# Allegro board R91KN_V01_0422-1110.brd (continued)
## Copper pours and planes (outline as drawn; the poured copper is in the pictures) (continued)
+1V on L3_INNER: 86.25,55.9 88.35,55.9 88.55,55.7 89.05,55.7 89.35,55.4 93.25,55.4 93.45,55.2 93.45,54.6 93.15,54.3 87.05,54.3 86.75,54.6 86.05,54.6 85.75,54.9 85.75,55.4
+1V_LDOOUT on BOTTOM: 48.25,44.8 51.55,44.8 51.95,44.4 53.75,44.4 53.85,44.5 53.85,49.3 52.85,50.3 51.05,50.3 50.45,50.9 49.85,50.9 49.75,50.8 49.75,48.3 50.75,47.3 50.75,46 50.35,45.6 48.15,45.6 47.95,45.4 47.95,45.1
+3.3V_BUS on TOP: 12.25,93.1 12.05,92.9 10.75,92.9 10.05,93.6 10.05,98.3 10.25,98.5 11.65,98.5 12.25,97.9
+3.3V_BUS on TOP: 55.14,6.59 54.95,6.4 52.75,6.4 52.35,6.8 52.35,8.08 52.45,8.18 52.45,13 52.85,13.4 56.95,13.4 57.05,13.3 57.05,12.5 56.85,12.3 56.45,12.3 55.75,11.6 55.75,10.95 55.14,10.34
+3.3V_BUS on BOTTOM: 10.55,98.6 14.75,98.6 18.75,94.6 18.75,91.4 18.15,90.8 18.15,87 16.95,85.8 16.95,71 20.05,67.9 27.65,67.9 33.25,73.5 35.65,73.5 36.95,72.2 36.95,70.3 30.65,64 18.85,64 14.55,68.3 14.55,87.5 15.65,88.6 15.65,92.2 13.05,94.8 10.35,94.8 9.95,95.2 9.95,98
+3.3V_BUS on BOTTOM: 54.99,2.92 54.91,2.84 54.41,2.84 54.31,2.95 54.31,5.66 54.25,5.71 54.08,5.71 54,5.64 54,3 53.85,2.84 53.44,2.84 53.31,2.97 53.31,5.84 52.15,7 52.15,7.39 52.04,7.5 52.04,17.37 52.45,17.78 66.57,17.78 66.78,17.58 66.78,16.53 65.95,15.7 62.85,15.7 60.31,13.16 57.4,13.16 57.1,12.85 57.1,10.62 56.92,10.44 55.5,10.44 55.09,10.03 55.09,5.92 54.99,5.82
+3.3V_BUS on BOTTOM: 73.56,88.06 74.04,88.06 74.38,87.73 74.38,87.07 74.55,86.9 77.55,86.9 78.13,87.48 78.13,91.74 80.04,93.65 90.6,93.65 90.81,93.45 90.81,84.8 87.97,81.96 87.97,81.24 87.65,80.92 86.95,80.92 86.17,81.7 85.65,81.7 85.25,81.3 85.25,81 85.17,80.92 77.23,80.92 76.85,81.3 76.85,82 75.81,83.04 74.79,83.04 73.25,84.58 73.25,87.76
+3.3V_BUS on L3_INNER: 52.45,13 52.45,6.8 52.85,6.4 54.95,6.4 55.15,6.6 55.15,8.2 58.25,11.3 58.35,11.3 61.65,14.6 61.65,52.7 62.25,53.3 62.25,58.5 61.85,58.9 57.18,58.9 40.79,75.29 40.79,94.39 42.21,95.81 70.94,95.81 75.67,91.08 115.14,91.08 122.25,98.2 122.25,101.22 121.57,101.9 31.67,101.9 28.8,99.03 28.8,75.25 52.35,51.7 52.35,13.1
+3.3V_DPB on TOP: 12.95,96 14.85,96 15.35,95.5 15.35,90.9 14.65,90.2 13.75,90.2 13.45,90.5 13.45,91.7 12.55,92.6 12.55,95.6
+3.3V_DPB on TOP: 13.55,88.8 14.95,88.8 15.25,88.5 15.25,86.9 15.05,86.7 12.45,86.7 12.35,86.8 12.35,87.6
+3.3V_DPB on BOTTOM: 13.55,91.5 14.75,91.5 15.15,91.1 15.15,88.6 14.35,87.8 13.35,87.8 12.65,88.5 12.65,89.7 13.45,90.5 13.45,91.4
+5V on BOTTOM: 42.55,46.2 44.35,46.2 44.55,46.4 44.55,47.1 44.75,47.3 45.55,47.3 45.75,47.5 45.75,49.6 45.55,49.8 43.15,49.8 42.35,49 42.35,46.4
+5V_VGAH on TOP: 5.75,94 8.85,94 9.35,93.5 9.35,92.4 8.85,91.9 6.05,91.9 5.45,92.5 5.45,93.7
+5V_VGAH on L3_INNER: 5.45,93.8 7.55,93.8 8.75,92.6 9.35,92.6 9.55,92.4 9.55,88.3 5.85,84.6 2.15,84.6 1.85,84.9 1.85,87.4 4.95,90.5 4.95,93.3
+12V_BUS on TOP: 46.3,6.35 46.15,6.5 46.15,16.84 46.43,17.12 49.33,17.12 49.58,16.87 49.58,15.94 50.22,15.3 51.15,15.3 51.61,14.84 51.61,8.47 50.65,7.51 49.44,7.51 48.13,6.2 48.13,6.2 47.98,6.05 47.98,2.74 47.85,2.62 47.45,2.62 47.32,2.74 47.32,5.61 47.24,5.69 47.07,5.69 46.99,5.61 46.99,2.67 46.89,2.57 46.43,2.57 46.3,2.69
+12V_BUS on TOP: 161.95,30.6 162.55,30 162.55,28.7 162.35,28.5 160.65,28.5 160.15,29 160.15,31.9 160.35,32.1 161.75,32.1 161.95,31.9
+12V_BUS on TOP: 132.75,97.4 136.05,97.4 136.35,97.1 137.85,97.1 138.25,97.5 138.25,99.2 136.65,100.8 135.45,100.8 132.05,104.2 129.55,104.2 129.35,104 129.35,100.8
+12V_BUS on TOP: 20.15,106.7 27.45,106.7 28.65,105.5 28.65,100.5 27.95,99.8 26.65,99.8 25.85,99 25.85,94.4 26.25,94 26.25,91.8 26.05,91.6 25.35,91.6 24.15,92.8 21.25,92.8 19.85,94.2 19.85,106.4
+12V_BUS on BOTTOM: 47.96,6.05 47.96,3 47.78,2.82 47.5,2.82 47.29,3.02 47.29,5.66 47.24,5.71 47.04,5.71 46.99,5.66 46.99,2.9 46.89,2.79 46.41,2.79 46.3,2.9 46.3,5.77 46.25,5.82 46.25,6.3 46.25,6.3 46.25,8.49 46.15,8.59 46.15,13.94 46.18,13.97 46.18,15.13 46.35,15.3 49.12,15.3 50.25,14.17 51.38,14.17 51.61,13.94 51.61,8.66 50.45,7.5 49.41,7.5
+12V_BUS on L3_INNER: 164.07,110.39 166.65,107.81 166.65,54.73 166.62,54.69 166.62,30.63 165.1,29.11 152.91,29.11 151.99,30.02 151.99,35.79 164.12,47.91 164.12,84.93 146.62,102.43 31.28,102.43 27.55,98.7 27.55,75.8 51.38,51.97 51.38,25.61 51.45,25.55 51.45,8.9 49.05,6.5 46.25,6.5 45.55,7.2 45.55,12.1 44.25,13.4 31.35,13.4 29.9,14.85 29.9,27.1 36.55,33.75 36.55,40.43 24.28,52.7 24.28,63.8 11.38,76.71 11.38,107.47 14.3,110.39
+VDDC on TOP: 56.45,85.1 57.75,86.4 57.75,96.66 57.56,96.85 55,96.85 51.35,93.2 46.55,93.2 44.55,91.2 44.55,89.53 42.88,87.86 42.88,85.47 43.25,85.1
+VDDC on BOTTOM: 43.45,84.7 56.55,84.7 57.55,85.7 57.55,87.3 59.25,89 59.25,92.7 58.05,93.9 45.45,93.9 42.35,90.8 42.35,85.8
+VDDC on BOTTOM: 55.55,70.5 55.76,70.29 55.75,70.28 55.75,67.74 53.21,65.2 53.21,62.71 53.85,62.08 53.85,50.9 53.55,50.6 51.15,50.6 50.45,51.3 50.45,68.18 52.77,70.5
+VDDC on L3_INNER: 93.83,70.53 93.83,56.9 92.53,55.6 88.95,55.6 87.86,56.69 86.92,56.69 85.15,58.46 85.15,60.6 84.85,60.9 70.82,60.9 64.67,67.06 63.45,67.06 62,68.5 49.15,68.5 41.45,76.2 41.45,91.2 45.12,94.87 64.39,94.87 75.13,84.12 91.87,84.12 96.27,79.73 96.27,76.15 95.38,75.26 95.35,75.26 95.35,72.05
+VDDC_SOURCE on TOP: 40.35,88.9 40.55,89.1 40.55,95.87 44.68,100 44.68,106.43 43.76,107.34 41.02,107.34 39.29,105.61 29.62,105.61 29.16,105.16 29.16,100 29.54,99.62 31.65,99.62 32.18,99.09 32.18,89.31 32.59,88.9
GND on TOP (solid shape): 76.65,91.1 74.65,91.1 74.65,92.7 76.65,92.7
GND on TOP (solid shape): outline of 188 points within 109,34.8 114.5,40.15
GND on TOP (solid shape): outline of 205 points within 65.8,77.85 71.3,83.35
GND on TOP (solid shape): outline of 208 points within 109,77.85 114.5,83.35
GND on TOP (solid shape): outline of 218 points within 3.1,102.59 8.59,108.08
GND on TOP (solid shape): outline of 218 points within 65.8,34.65 71.3,40.15
GND on BOTTOM (solid shape): outline of 198 points within 109,34.65 114.5,40.15
GND on BOTTOM (solid shape): outline of 205 points within 65.8,77.85 71.3,83.35
GND on BOTTOM (solid shape): outline of 218 points within 65.8,34.65 71.3,40.15
GND on BOTTOM (solid shape): outline of 218 points within 109,77.85 114.5,83.35
GND on TOP: 161.16,92.03 165.36,92.03 165.56,91.83 165.56,88.13 165.36,87.93 161.06,87.93 160.96,88.03 160.96,91.83
GND on TOP: 4.15,99 7.65,99 9.65,97 9.65,94.9 9.05,94.3 4.15,94.3 3.55,94.9 3.55,98.4
GND on TOP: 44.96,16.59 45.8,17.42 49.43,17.42 49.43,17.42 49.85,17 49.85,16.2 50.35,15.7 51.45,15.7 51.65,15.9 51.65,17.4 51.45,17.6 51.05,17.6 51.05,18.5 50.85,18.7 49.75,18.7 49.63,18.82 49.63,19.28 49.43,19.48 45.44,19.48 44.45,20.47 44.45,21.92 44.12,22.25 36.35,22.25 34.11,20.01 34.11,14 34.52,13.59 44.55,13.59 44.96,14
GND on TOP: 129.55,88.5 132.25,88.5 132.95,89.2 132.95,93.5 132.55,93.9 129.65,93.9 129.25,93.5 129.25,88.8
GND on TOP: 27.41,88.77 26.62,89.56 26.62,98.68 27.03,99.09 31.09,99.09 31.83,98.35 31.83,88.98 31.62,88.77
GND on TOP: 41.02,95.63 41.02,89.6 41.54,89.08 43.21,89.08 43.74,89.61 43.74,95.76 43.23,96.27 41.66,96.27
GND on TOP: 146.82,78.9 149,78.9 149.4,78.49 149.4,65.61 148.97,65.18 146.81,65.18 146.38,65.61 146.38,78.47
GND on TOP: 58.15,96.9 59.45,96.9 60.35,96 60.35,87.9 59.95,87.5 58.65,87.5 58.45,87.7 58.45,89.1 57.95,89.6 57.95,96.7
GND on TOP: 33.15,106.5 38.75,106.5 39.05,106.8 39.05,109.4 38.85,109.6 32.95,109.6 32.55,109.2 32.55,107.1
GND on TOP: 138.85,96.2 145.55,96.2 145.85,96.5 145.85,97.7 145.55,98 138.75,98 138.55,97.8 138.55,96.5
GND on TOP: 54.29,103.9 56.75,103.9 57.12,103.53 57.12,99.42 56.95,99.24 54.53,99.24 54.19,99.58 54.19,103.8
GND on BOTTOM: 69.78,69.84 69.78,67.07 69.62,66.91 68.31,66.91 68.11,66.71 68.11,66.03 68.02,65.94 67.11,65.94 66.91,66.14 66.91,67.64 67.02,67.73 68.11,67.73 68.24,67.86 68.24,69.78 68.39,69.92 69.7,69.92
GND on BOTTOM: 72.25,54.6 74.26,54.6 74.85,55.2 76.23,55.2 76.4,55.02 76.4,53.85 76.15,53.6 75.75,53.6 75.45,53.3 75.45,51.5 75.25,51.3 73.65,51.3 73.15,51.8 72.15,51.8 71.85,52.1 71.85,54.2
GND on BOTTOM: 48.7,39.05 47.25,39.05 46.35,38.15 46.35,34.3 46.65,34 48.95,34 49.25,34.3 49.25,38.5
GND on BOTTOM: 48.45,48 49.05,48 49.35,48.3 49.35,50.8 48.95,51.2 46.55,51.2 46.05,50.7 46.05,48.5 46.12,48.43 48.02,48.43
GND on BOTTOM: 40.55,19.6 44.15,19.6 44.45,19.9 44.95,19.9 45.35,19.5 45.35,17.4 44.85,16.9 41.15,16.9 40.05,18 40.05,19.1
GND on BOTTOM: 28.63,88.9 27.05,90.47 27.05,99.09 28.19,100.23 35.08,100.23 35.74,99.57 35.74,90.14 34.49,88.9
GND on BOTTOM: 44.95,47 47.65,47 47.85,46.8 47.85,41.5 47.65,41.3 45.05,41.3 44.85,41.5 44.85,46.9
GND on BOTTOM: 49.62,31.27 56.16,31.27 56.26,31.17 56.26,28.4 55.96,28.09 49.56,28.09 49.35,28.3 49.35,31
GND on BOTTOM: 71.19,46.02 74.26,46.02 74.26,46.01 74.84,46.01 74.95,45.9 74.95,44.65 74.21,43.91 73.32,43.91 72.97,43.56 70.48,43.56 70.31,43.74 70.31,45.87 70.45,46.01 71.18,46.01
GND on BOTTOM: 51.75,17.5 51.85,17.4 51.85,16 51.15,15.3 49.95,15.3 49.45,15.8 47.45,15.8 47.45,17.6 49.25,19.4 50.65,19.4 51.75,18.3
GND on L2_INNER: 0.62,5.05 0.55,5.12 0.55,109.6 1.55,110.59 166.75,110.59 167.07,110.28 167.07,14.41 166.87,14.21 166.38,14.21 166.38,14.2 148.85,14.2 148.15,13.5 140.05,13.5 138.57,12.02 138.57,11.62 136.45,9.5 128.55,9.5 127.65,8.6 127.65,6.88 126.46,5.69 126.46,5.6 58.95,5.6 58.95,8.71 57.84,9.81 56.32,9.81 54.81,8.29 54.81,6.2 46.12,6.2 46.12,11.21 46.13,11.22 45.87,12.33 44.36,13.76 42.58,13.78 41.97,13.65 40.86,12.8 34.61,12.8 33.93,13.48 15.2,13.48 14.37,12.64 14.37,5.05
GND on L3_INNER: 0.56,68.03 0.62,68.09 16.82,68.09 16.95,67.96 16.95,41.5 16.65,41.2 16.65,22.6 17.75,21.5 18.35,21.5 18.95,22.1 18.95,23.6 20.15,24.8 20.15,28.91 23.52,32.28 25.35,32.28 26.67,30.96 26.67,22.52 28.32,20.87 28.32,15.05 27.56,14.3 20.6,14.3 20.05,13.75 14.75,13.75 14.44,13.44 14.44,13.11 14.45,13.1 14.45,5.63 13.87,5.04 0.64,5.04 0.56,5.13
GND on L3_INNER: 58.75,11.03 62.35,14.62 62.35,40.4 62.95,41 73.35,41 75.75,43.4 75.75,47.7 81.72,53.67 84.05,53.67 84.71,54.33 86.72,54.33 87.09,53.96 88.91,53.96 88.93,53.95 93.83,53.95 95,52.78 95,49.4 95.47,48.93 95.47,47.08 95.86,46.69 95.86,45.16 99.64,41.39 99.64,41.35 110.25,30.74 110.29,30.74 128.75,12.27 128.75,8.28 128.56,8.09 128.65,8 128.65,6.6 128.35,6.3 59.15,6.3 58.75,6.7
VDDC_PHASE on TOP: 45.8,103.86 45.8,99.72 44.98,98.91 44.98,94.95 45.85,94.08 51.51,94.08 53.82,96.39 53.82,105.54 53.54,105.82 51.08,105.82 50.44,106.45 50.44,108.38 50.19,108.64 48.11,108.64 47.83,108.36 47.83,104.29 47.52,103.99 45.92,103.99
+MVDD on TOP: 149.95,78.3 149.95,68.1 150.25,67.8 163.55,67.8 164.65,68.9 164.65,78 163.95,78.7 150.35,78.7
+MVDD on BOTTOM: 149.76,83.42 164.06,83.42 166.07,81.41 166.07,69.02 164.8,67.75 150.22,67.75 148.92,69.04 148.92,82.58
+MVDD on BOTTOM: 62.55,82.2 42.25,61.9 42.25,50.6 41.75,50.1 39.33,50.1 38.73,50.7 38.73,62.76 59.65,83.68 59.65,87.6 65.15,93.1 65.15,93.11 66.24,93.11 67.74,94.61 69.65,94.61 69.9,94.36 69.9,93.19 69.88,93.17 69.88,92.33 66.35,88.8 65.51,88.8 62.55,85.84
+MVDD on L3_INNER: 95.15,53.7 94.29,54.56 94.28,54.56 93.82,55.02 93.82,58.12 93.8,58.15 93.8,58.7 94.17,59.08 94.17,61.58 94.1,61.65 94.05,61.65 94.05,70.3 95.56,71.81 95.56,75.11 96.55,76.1 96.55,80 91.92,84.63 75.29,84.63 66.95,92.97 66.95,94.05 68,95.1 70.46,95.1 75.66,89.9 115.24,89.9 127.2,101.87 146.58,101.87 163.62,84.83 163.62,66.63 163.62,66.63 163.62,48.33 141.78,26.49 115.26,26.49 96.16,45.59 96.16,46.79 95.73,47.22 95.73,49.02 95.15,49.6
+MVDD_SOURCE on TOP: 133.45,96.1 133.45,89.8 135.15,88.1 150.15,88.1 150.35,88.3 150.35,93.4 149.75,94 145.85,94 145.45,94.4 145.45,95.1 144.65,95.9 136.05,95.9 135.35,96.6 133.95,96.6
DPA_GND on BOTTOM: 19.85,58.5 19.85,48.4 20.85,47.4 22.15,47.4 22.55,47.8 22.55,58.7 22.15,59.1 20.45,59.1
FANOUT_N on TOP: 149.65,19.9 151.75,19.9 153.15,18.5 161.15,18.5 162.35,17.3 165.65,17.3 166.15,17.8 166.15,19.8 165.65,20.3 162.25,20.3 160.75,21.8 159.15,21.8 158.45,22.5 158.45,23.5 157.95,24 154.35,24 151.75,21.4 149.65,21.4 149.45,21.2 149.45,20.1
FANOUT_P on TOP: 159.15,22.4 160.85,22.4 162.45,20.8 165.25,20.8 165.95,21.5 165.95,27.2 165.15,28 161.25,28 158.95,25.7 158.95,22.6
LDO1_VIN on BOTTOM: 65.95,18.8 67.05,19.9 68.35,19.9 68.65,20.2 68.65,21.9 67.51,23.04 52.7,23.04 52.22,23.52 52.22,27.74 52.13,27.83 51.27,27.83 51.13,27.69 51.13,25.7 50.25,24.82 50.25,20.87 51.74,19.38 51.85,19.38 52.43,18.8
LDO2_VIN on BOTTOM: 38.95,49.5 41.55,49.5 41.85,49.2 41.85,46.2 42.35,45.7 44.15,45.7 44.35,45.5 44.35,45 44.25,44.9 39.45,44.9 38.75,45.6 38.75,49.3
MVDD_PHASE on TOP: 151.65,92.1 153.09,92.1 154.86,93.88 159.54,93.88 159.82,93.6 159.82,88.6 158.5,87.27 158.5,80.57 157.28,79.35 152.45,79.35 151.36,80.44 151.36,91.81
Net_584 on BOTTOM (solid shape): outline of 95 points within 149.59,1 166.64,9.35
Net_585 on BOTTOM (solid shape): outline of 120 points within 20.13,1.08 28.12,9.33
Net_585 on TOP: 28.12,1.08 20.13,1.08 20.13,9.33 28.12,9.33 ; 1 cut-out
UNNAMED_11_CAP_I11_B on TOP: 50.95,106.3 54.15,106.3 54.35,106.5 54.35,108.4 54.15,108.6 51.05,108.6 50.85,108.4 50.85,106.4
UNNAMED_12_CAP_I19_A on TOP: 159.05,86.97 159.05,84.96 159.61,84.4 161.34,84.4 161.82,84.89 161.82,87.05 161.59,87.27 159.36,87.27
N7393636 on TOP: 43.05,22.5 43.07,22.52 51.85,22.52 52.05,22.72 52.05,25.61 51.55,26.11 46.25,26.11 45.23,25.1 43.9,25.1 43.3,24.5 36.21,24.5 35.99,24.28 35.99,22.63 36.12,22.5
N7393636 on BOTTOM: 34.05,24.7 37.15,24.7 37.25,24.6 37.25,22.4 37.15,22.3 34.05,22.3 33.95,22.4 33.95,24.6
N7393760 on TOP: 46.86,22.19 46.3,21.64 46.3,19.91 46.48,19.74 51.64,19.74 52.1,20.19 52.1,22.02 51.92,22.19

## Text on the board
User.Comments: DECOUPLING AREA(ALLOWED 1.5mm COMPONENT HEIGHT) | UNIT:mm | 48.00 | 42.00 | 38.00 | 50.80 | 38.10 | R6.00 | 23.00 | 5.00 | R1.50 | R1.00 | R2.00 | 0.00 | 80.46 | 42.44 | 17.68
Ref Des/Silkscreen Top: 109-C26457-01 | A
DIMENSION: 4.50 | 0.00 | 57.15 | 42.15 | 23.80 | 15.80 | 12.15 | 110.49 | SHORTED GND GND_A2VSSN | SHORTED GND GND_A2VSSQ | SHORTED GND GND_AVSSN | SHORTED GND GND_AVSSQ | SHORTED GND GND_TXVSSR | SHORTED GND GND_MPVSS | SHORTED GND GND_PVSS | SHORTED GND GND_TPVSS | SHORTED GND GND_R2SET | SHORTED GND GND_RSET | SHORTED +MVDDC N16776782 | SHORTED +MVDDC N16776726 | TAB C/L  0.250 | TAB C/L 3.800 | 111.15 | I/O WINDOW | (Bottom) | 12.75 | (Top) | 2.040 | 3.150 | 1.025 | 0.000 | 2X RO.51 | 1.90+/-.06X8.70 | SEE NOTE 20 | BOARD ORIGIN X=-57.15 Y=0.000 | BRACKET PN 8020032100 | COMPONENT ORIGIN X=57.15 Y=0.000 FROM BL CORNER
User.12: A | B | C | D | E | F | G | 3 | 2 | 1
User.21: PN 109-A181GN-00A
User.23: PN 109-C26457-01 | Caicos/Cedar Junbonator | Oct 11, 2010 | Lisa,Yue | 2010 Advanced Micro Devices
User.42: PN 109-A181GN-00A
User.45: VSS_MECH#3 | TXCBM_DPB3N | TX3M_DPB2N | DPB_VSSR#4 | DPB_VSSR#1 | G2 | C | DPE_VSSR#1 | DPE_VSSR#4 | DPE_VSSR#5 | DPF_VSSR#5 | DPF_VSSR#1 | DPF_VSSR#2 | R | XTALIN | PCIE_PVDD | VSS_MECH#4 | TX5M_DPB0N | B2 | R2 | H2SYNC | TXCLK_LP_DPE3P | TXOUT_L1P_DPE1P | TXOUT_L3P | TXOUT_U0P_DPF2P | TXOUT_U2P_DPF0P | G | VSYNC | TX2M_DPA0N | TX2P_DPA0P | TXCBP_DPB3P | TX3P_DPB2P | TX5P_DPB0P | G2B | Y | TXCLK_LN_DPE3N | TXOUT_L1N_DPE1N | TXOUT_L3N | TXOUT_U0N_DPF2N | TXOUT_U2N_DPF0N | TXOUT_U3P | RB | XTALOUT | PCIE_REFCLKN | PCIE_REFCLKP | TX4P_DPB1P | B2B | R2B | V2SYNC | TXOUT_L0N_DPE2N | TXOUT_L2N_DPE0N | TXCLK_UN_DPF3N | TXOUT_U1N_DPF1N | TXOUT_U3N | GB | HSYNC | DPA_VSSR#3 | TX1P_DPA1P | DPA_VSSR#4 | TX4M_DPB1N | DPB_VSSR#5 | VSSD#9 | COMP | DPE_VSSR#2 | TXOUT_L0P_DPE2P | TXOUT_L2P_DPE0P | TXCLK_UP_DPF3P | TXOUT_U1P_DPF1P | B | RSET | VSSD#7 | PCIE_TX0N | PCIE_VSS#12 | TX1M_DPA1N | TX0P_DPA2P | TX0M_DPA2N | DPA_VSSR#5 | DPA_PVSS | DPA_PVDD | DPB_VSSR#2 | DPB_PVDD | DPB_PVSS | VSSD#4 | R2SET | DPE_VSSR#3 | DPE_VDD18#1 | DPE_VDD18#2 | DPF_VDD18#2 | DPE_PVDD | NC_DPF_PVDD | DPE_VDD10#1 | DPE_VDD10#2 | DPF_VDD10#1 | DPF_VSSR#3 | AVDD | BB | PCIE_VDDR#6 | PCIE_VSS#11 | PCIE_TX1P | PCIE_TX0P | TXCAP_DPA3P | TXCAM_DPA3N | DPA_VDD10#2 | DPA_VDD10#1 | DPB_VDD10#2 | DPB_VDD10#1 | DPB_VSSR#3 | DPA_VDD18#2 | DPB_VDD18#1 | DPLL_PVDD | DPF_VDD18#1 | DPEF_CALR | DPE_PVSS | NC_DPF_PVSS | DPF_VDD10#2 | DPF_VSSR#4 | TESTEN | PCIE_VDDR#7 | PCIE_TX2N | PCIE_TX2P | PCIE_TX1N | PCIE_RX0P | PCIE_VSS#10 | DPA_VSSR#1 | DPA_VSSR#2 | DDC1DATA | DDC1CLK | VSSD#5 | DVPDATA_16 | DVPDATA_18 | DPAB_CALR | DPA_VDD18#1 | DPB_VDD18#2 | DPLL_PVSS | DDCAUX3P | A2VDDQ | A2VSSQ | A2VDD | AVSSQ | VDD1DI | PCIE_VDDR#3 | PCIE_VDDR#4 | PCIE_VDDR#5 | PCIE_VSS#9 | PCIE_RX1P | PCIE_RX0N | AUX1P | AUX1N | VSSD#1 | DVPDATA_12 | VSSD#8 | DVPDATA_20 | GENERICE_HPD4 | AUX2N | AUX2P | DPLL_VDDC | DDCAUX3N | TSVDD | VDD2DI | NC_DDCAUX4P | VSS1DI | PERSTB | PCIE_VDDR#2 | PCIE_VSS#7 | PCIE_TX3N | PCIE_TX3P | PCIE_RX1N | PCIE_RX2P | PCIE_VSS#8 | DDCVGACLK | DDCVGADATA | DVPDATA_23 | DVPDATA_10 | DVPCNTL_0 | DVPDATA_14 | VSSD#2 | DVPDATA_22 | DDC2CLK | DDC2DATA | HPD1 | VREFG | TSVSS | VSS2DI | NC_DDCAUX4N | NC_CEC2 | PCIE_VDDR#8 | PCIE_VSS#4 | PCIE_TX4P | PCIE_VSS#5 | PCIE_VSS#6 | PCIE_RX3P | PCIE_RX2N | DVPDATA_21 | DVPDATA_19 | VSSD#17 | VARY_BL | DIGON | GENERICA | VSSC#8 | NC_LIGHT_SENSOR | VDDR3#3 | VDDR3#4 | VDD_CT#2 | VDD_CT#4 | NC_CEC1 | PCIE_TX6P | PCIE_RX3N | PCIE_RX4P | PCIE_VSS#3 | DVPDATA_4 | DVPDATA_6 | DVPDATA_8 | VSSD#3 | PCIE_VDDR#1 | PCIE_VSS#2 | PCIE_TX4N | PCIE_TX6N | DVPCNTL_MVP_0 | DVPDATA_13 | DVPDATA_15 | DVPDATA_17 | PCIE_VSS#1 | PCIE_RX5P | PCIE_RX4N | VDDR4#3 | VDDR4#4 | VSSC#14 | EVDD | EVDDQ | VDDR3#1 | VDDR3#2 | VDD_CT#1 | VDD_CT#3 | PCIE_CALRN | DVPDATA_0 | DVPDATA_2 | GPIO_14_HPD2 | VSSD#18 | PCIE_TX5P | PCIE_TX5N | PCIE_VSS#30 | PCIE_TX7N | DVPCNTL_1 | DVPCNTL_MVP_1 | VSSD#10 | PCIE_TX7P | PCIE_RX5N | PCIE_RX6P | PCIE_VSS#31 | VDDR4#1 | VDDR4#2 | VDDC#11 | VSSC#22 | VDDC#21 | VSSC#23 | VDDC#22 | VSSC#24 | NC_VDDC_BIF#2 | PCIE_CALRP | DVPDATA_5 | DVPDATA_7 | DVPDATA_9 | DVPDATA_11 | PCIE_VSS#29 | PCIE_RX7P | PCIE_RX6N | GENERICD | GENERICB | GENERICC | GPIO_18_HPD3 | PCIE_TX8N | PCIE_TX8P | PCIE_VSS#27 | PCIE_VSS#28 | VDDR5#2 | VDDR5#3 | VSSC#18 | VDDC#18 | VSSC#19 | VDDC#19 | VSSC#20 | VDDC#20 | NC_VDDC_BIF#1 | PCIE_VDDC#12 | DVPDATA_1 | DVPDATA_3 | VSSD#16 | PCIE_TX9P | PCIE_RX7N | PCIE_RX8P | PCIE_VSS#26 | GPIO_4_SMBCLK | GPIO_3_SMBDATA | VSSD#15 | GPIO_1 | PCIE_TX10N | PCIE_TX10P | PCIE_VSS#24 | PCIE_TX9N | DVPCLK | VSSD#6 | DVPCNTL_2 | GPIO_0 | VDDR5#1 | VDDR5#4 | VDDC#1 | VSSC#15 | VDDC#15 | VSSC#16 | VDDC#16 | VSSC#17 | VDDC#17 | PCIE_VDDC#11 | PCIE_VSS#25 | PCIE_RX9P | PCIE_RX8N | DMINUS | DPLUS | VSSD#14 | GPIO_29_DRM_0 | VDDC#2 | VSSC#3 | VDDC#12 | VSSC#12 | VDDC#13 | VSSC#13 | VDDC#14 | VSSC#21 | PCIE_VDDC#10 | PCIE_TX11N | PCIE_RX9N | PCIE_RX10P | PCIE_VSS#23 | GPIO_7_BLON | GPIO_6_TACH | GPIO_5_AC_BATT | GPIO_2 | PCIE_TX12N | PCIE_TX12P | PCIE_VSS#22 | PCIE_TX11P | SCL | SDA | TS_FDO | GPIO_17_THERMAL_INT | PCIE_VSS#21 | PCIE_RX11P | PCIE_RX10N | GPIO_30_DRM_1 | VSSC#1 | VDDC#8 | VSSC#9 | VDDC#9 | VSSC#10 | VDDC#10 | VSSC#11 | VDDC#23 | PCIE_VDDC#9 | GPIO_21_BB_EN | GPIO_20_PWRCNTL_1 | VSSD#13 | GPIO_8_ROMSO | PCIE_TX14N | PCIE_TX14P | PCIE_VSS#19 | PCIE_TX13N | GPIO_10_ROMSCK | GPIO_9_ROMSI | VSSD#12 | PCIE_TX13P | PCIE_RX11N | PCIE_RX12P | PCIE_VSS#20 | BBN#1 | BBN#2 | VSSC#5 | VDDC#5 | VSSC#6 | VDDC#6 | VSSC#7 | VDDC#7 | VSSC#2 | PCIE_VDDC#6 | GPIO_15_PWRCNTL_0 | GPIO_13 | GPIO_12 | GPIO_11 | PCIE_VSS#18 | PCIE_RX13P | PCIE_RX12N | GPIO_23_CLKREQB | GPIO_22_ROMCSB | NC#2 | NC_PWRGOOD | PCIE_VDDC#7 | PCIE_VDDC#8 | PCIE_VSS#17 | PCIE_TX15N | BBP#1 | BBP#2 | VDDC#3 | VDDCI#1 | VDDCI#2 | VDDCI#3 | VDDCI#4 | VSSC#4 | VDDC#4 | PCIE_VDDC#5 | GPIO_19_CTF | GPIO_16_SSIN | VSSD#11 | PCIE_TX15P | PCIE_RX13N | PCIE_RX14P | PCIE_VSS#16 | CLKTESTB | MPVDD | NC#1 | DRAM_RST | PCIE_VDDC#1 | PCIE_VDDC#2 | PCIE_VDDC#3 | PCIE_VDDC#4 | GPIO_27_TMS | GPIO_26_TCK | GPIO_25_TDI | GPIO_24_TRSTB | VDDR1#9 | VDDR1#5 | VDDR1#7 | MAA1_7 | VSSRHA | VDDRHA | ADBIA0 | VDDR1#1 | VDDR1#4 | VDDR1#14 | PCIE_VSS#15 | PCIE_RX15P | PCIE_RX14N | VSSM#41 | GPIO_28_TDO | VSSM#42 | MEM_CALRNB | CLKTESTA | VDDR1#17 | VDDR1#11 | VSSM#35 | CSA1B_1 | MAA1_1 | ADBIA1 | MAA0_0 | MAA0_7 | CKEA0 | VSSM#37 | VDDR1#10 | VDDR1#12 | MEM_CALRPA | MVREFDA | DQA0_0 | PCIE_VSS#13 | PCIE_RX15N | PCIE_VSS#14 | DQA1_29 | DQA1_30 | DQA1_31 | DQA1_28 | SPVSS | MEM_CALRPB | VDDR1#15 | VDDR1#2 | MAA1_2 | MAA1_3 | MAA1_0 | MAA1_6 | CKEA1 | MAA0_6 | MAA0_1 | CSA0B_1 | VDDR1#3 | VDDR1#8 | MEM_CALRNA | MVREFSA | VSSM#39 | DQA0_1 | VSSM#40 | VSSM#31 | DDBIA1_3 | VSSM#38 | SPV18 | SPV10 | CLKA1B | WEA1B | MAA1_4 | VDDR1#6 | VSSM#34 | VDDR1#13 | VSSM#36 | VDDR1#16 | VSSM#33 | CSA0B_0 | MAA0_2 | MAA0_5 | CLKA0B | CLKA0 | DDBIA0_0 | EDCA0_0 | DQA0_2 | DQA0_3 | DQA1_26 | DQA1_27 | EDCA1_3 | DQA1_25 | DQA1_24 | VSSM#32 | CLKA1 | VSSM#43 | MAA1_5 | CSA1B_0 | MAA1_8 | CASA1B | RASA1B | CASA0B | MAA0_8 | RASA0B | MAA0_3 | MAA0_4 | WEA0B | DQA0_13 | VSSM#29 | DQA0_4 | VSSM#30 | VSSM#22 | WCKA1B_1 | VSSM#27 | DQA1_19 | VSSM#28 | DQA1_14 | VSSM#17 | DQA1_11 | VSSM#18 | DQA1_5 | VSSM#19 | DQA1_2 | VSSM#20 | DQA0_29 | VSSM#21 | DQA0_26 | VSSM#23 | DQA0_23 | VSSM#24 | DQA0_21 | VSSM#25 | DQA0_15 | VSSM#26 | DQA0_9 | DQA0_5 | DQA0_7 | DQA0_6 | DQA1_23 | WCKA1_1 | DQA1_21 | DQA1_16 | DDBIA1_1 | DQA1_8 | WCKA1_0 | EDCA1_0 | DQA1_0 | EDCA0_3 | DQA0_24 | DQA0_20 | DQA0_18 | DQA0_12 | VSSM#16 | WCKA0B_0 | WCKA0_0 | EDCA1_2 | DQA1_15 | EDCA1_1 | WCKA1B_0 | DQA1_4 | DQA1_1 | DQA0_28 | DQA0_25 | DQA0_22 | DQA0_19 | DQA0_14 | VSSM#14 | DQA1_22 | DDBIA1_2 | DQA1_18 | DQA1_13 | DQA1_10 | DQA1_7 | DDBIA1_0 | DQA0_31 | DDBIA0_3 | WCKA0B_1 | DDBIA0_2 | DQA0_17 | EDCA0_1 | DQA0_11 | DQA0_8 | VSSM#15 | VSSM#12 | VSSM#13 | VSSM#3 | VSSM#4 | VSSM#5 | VSSM#6 | VSSM#7 | VSSM#8 | VSSM#9 | VSSM#10 | VSSM#11 | VSSM#1 | DQA1_20 | DQA1_17 | DQA1_12 | DQA1_9 | DQA1_6 | DQA1_3 | DQA0_30 | DQA0_27 | WCKA0_1 | EDCA0_2 | DQA0_16 | DDBIA0_1 | DQA0_10 | VSSM#2 | VSS_MECH#2 | Total Thickness after Plating to be 1.57 mm [62 mil] +/-0.13 mm [5 mil] | As measured at Gold Plated Fingers (if present on board) | 0.0737 mm | 1.2400 mm | Solder Mask | [2.90 mil] | [48.82 mil] | 1/2 oz Routing (Before Plating) | 1 oz Plane | 1 oz Routing | 3.20 Dk | 4.13 Dk | 4.48 Dk | TOP | L2_INNER | L3_INNER | BOTTOM | NOTES              For ALL Fabrication issues email: AMDPCBCADSupportGroup@AMD.com | Also see the README Notes for more information about this design. | [Variant:57] | 1. ACCEPTABILITY:     PRINTED WIRING BOARD SHALL MEET THE REQUIREMENTS OF IPC-6012 CLASS 2. | 2. MATERIAL:          GLASS EPOXY FR-4 FIRE RETARDANT AND UL 94V-0 RATING | BOARD OPERATING TEMPERATURE MUST BE UL APPROVED TO A MAX 130 Deg C. | MATERIAL SHOULD MEET IPC-4101/99 AND MATERIAL SHALL ALSO MEET | THE RELIABILITY REQUIREMENTS FOR MULTIPLE THERMAL PROFILES USED | IN LEAD FREE ASSEMBLIES. | 3. CLEANLINESS:       PRINTED WIRING BOARD CLEANLINESS SHALL MEET J-STD-001 PRIOR TO | APPLICATION OF SOLDER MASK. | 4. SOLDER MASK:       COLOUR: BLACK | SHALL MEET REQUIREMENTS OF IPC-SM-840 CLASS T. PLUG ALL NON | FUNCTIONAL PTH VIAS PRIOR TO SOLDER MASK APPLICATION, THEN | COMPLETELY COVER PLUGGED PTH VIAS OVER WITH SOLDER MASK. | ALL FUNCTIONAL PTH VIAS SHOULD NOT BE PLUGGED. | ALL VIAS ON SMD PADS MAY BE HALF PLUGGED IF REQUIRED. | DEFINITION OF FUNCTIONAL PTH VIA: ANY VIA WITH A SOLDER MASK | OPENING OF 0,55mm OR MORE ON ONE SIDE AND AN OPENING OF THE | SOLDER MASK OF DRILL DIAMETER PLUS 0,08 mm ON THE OPPOSITE SIDE. | SOLDER MASK BRIDGE BETWEEN PADS SHOULD BE MINIMUM 0,10 mm. SOLDER | MASK REGISTRATION ACROSS PANEL TO BE MAINTAINED WITHIN +/- 0,05mm. | FOR SOLDERMASK DEFINED PADS, APPLY A TOLERANCE OF +0,05mm/-0,03mm. | 5. FINISH:            IMMERSION SILVER | AS PER IPC-4553 SPECIFICATION FOR IMMERSION SILVER PLATING FOR | PRINTED CIRCUIT BOARDS. | 6. SILKSCREEN:        COLOUR: WHITE | NON-CONDUCTIVE EPOXY INK. DO  NOT CLEAR SILKSCREEN FOR AGENCY | MARKINGS CE, FCC, ICES AND DECLARATION OF CONFORMITY THAT ARE OVER | VIAS.CLEAR SILKSCREEN OVER THROUGH HOLE AND SMD PADS AND ANY FUNCTIONAL | VIAS (TEST POINTS). | 7. BOW AND TWIST:     SHALL NOT EXCEED 0.75% OF MAXIMUM DIMENSION WHEN TESTED | ACCORDING TO IPC-TM-650. | 8. VENDOR'S LOGO:     BOARD MANUFACTURER'S LOGO, DATE CODE,UL FLAMMABILITY RATING, FILE | NUMBER AND UR SYMBOL SHALL APPEAR ON SILKSCREEN TOP IN AREA SHOWN | OR IF MIRRORED ON SILKSCREEN BOTTOM IN AREA SHOWN. UR LOGO SIZE | CAN BE ADJUSTED TO FIT IF REQUIRED BUT STILL LEGIBLE. | 9. HOLES:             ALL HOLES SHALL BE DRILLED WITHIN 0,18mm DIAMETER OF TRUE POSITION AT A | MAXIMUM MATERIAL CONDITION RELATIVE TO MATERIAL AREA CENTRES. | FINISHED HOLE SIZES SHOWN ARE APPLICABLE AFTER PLATING. | 10. EDGE FINGERS:     IF PRESENT, SHALL BE GOLD OVER NICKEL PLATED, WITH A MINIMUM THICKNESS OF: | GOLD:    10 micro inches (Standard) | NICKEL: 100 micro inches (Standard) | 11. ENVIRONMENTAL:    THE PCB SUPPLIER SHALL PROVIDE A SIGNED CERTIFICATE OF COMPLIANCE | BY AN AUTHORIZED QA REPRESENTATIVE. THE BASE MATERIAL OF PCB SHALL NOT | CONTAIN THE BANNED SUBSTANCES LISTED IN THE CERTIFICATE OF COMPLIANCE. | FINAL PRODUCT MUST BE RoHS COMPLIANT. | PRODUCT MUST ALSO BE COMPLIANT TO AMD ENVIRONMENTAL SPECIFICATION: 16-203.1 | This product must also be Halogen free.The restriction of Halogens | or "Halogen Free" is defined as the restriction of Brominated and | Chlorinated compounds per IEC 61249-2-21:2003. No other Halogen | (Fluorine, Iodine, or Astatine) is restricted. A Halogen free | part/product is defined as each homogeneous material(s) for each | part/product cannot exceed the maximum concentration listed below: | Material Substance       Threshold Level | ------------------       --------------- | Bromine (br)             900 ppm | Chlorine (cl)            900 ppm | Total concentration of cl and br 1500 ppm | 12. INNER LAYER PADS: ALL UNUSED PADS ON THE INNER LAYERS SHOULD BE REMOVED. | 13. ANTIPADS:         ALL ANTIPADS DIAMETERS ON INNER LAYERS MUST NOT VARY MORE THAN +/-0,03mm. | 14. PAD TOLERANCE:    ALL OUTER LAYER PADS WITH A DIMENSION EQUAL OR LESS THAN 0,50mm REQUIRE | +/-0,03 mm TOLERANCE. THE REST OF THE PADS SHOULD FOLLOW THE IPC 6012. | 15. VIA ANNULAR RING: IT IS ALLOWED TO BREAK PADS AT NON-NECK LOCATION FOR VIAS WITH DIAMMETERS | EQUAL OR LESS THAN 0,50mm AS LONG AS A GUARANTEED ANNULAR RING | OF 0,03mm IS PROVIDED AT NECK LOCATION. SEE IPC-A-600F/2.10 FOR CLASS 2. | 16. TEAR DROPS:       DUE TO THE DIFFICULTY WITH THE ETCH FACTOR USING SILVER FINISH,TEARDROPS | MUST BE ADDED TO ALL TRACES WIDTHS 0,254mm OR LESS TO ENSURE PLOTTED | TRACE WIDTHS ARE MET. | 17. MICRO VIAS:       IF PRESENT, ALL MICROVIAS (0,16mm dia. or less) ARE TO BE PLATED OVER WITH | COPPER ENSURING A DIMPLE OF LESS THAN 15um. | 18. BREAK OFF TABS:   UNLESS DIMENSIONED FOLLOW CAD OUTLINE.ADD COPPER WHERE REQUIRED FOR PROCESSING. | 19. BURIED VIAS:      IF PRESENT ALL BURIED VIAS ARE TO BE PLUGGED. | FIGURE | SIZE | 0.25 | 0.259 | 0.289 | 0.43 | 0.6 | 0.65 | 0.9 | 1.0 | 1.1001 | 1.1999 | 2.15 | 0.61 | 1.2 | 1.5 | 1.65 | 1.95 | 2.5 | 3.175 | 3.4 | 1.6x1.4 | 2.2x1.0 | 2.8x1.0 | 3.0x1.0 | 4.5x2.0 | DRILL CHART: TOP to BOTTOM | ALL UNITS ARE IN MILLIMETERS | PLATED | NON-PLATED | QTY | 1442 | 2 | 199 | 15 | 6 | 24 | 12 | 1 | 4 | 10 | 4 LAYER CROSS SECTION BUILD | Testpoint via locations for TOP and BOTTOM layers. | Please refer to Note 4 in the Fab Notes.
